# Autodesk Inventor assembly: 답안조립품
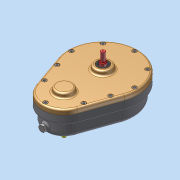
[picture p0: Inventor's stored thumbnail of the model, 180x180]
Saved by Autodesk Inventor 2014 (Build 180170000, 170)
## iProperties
Created: 2025-02
Part Number: 답안조립품
Document SubType Name: Assembly
Designer: dg
Mass: 1846.66 g
Surface Area: 1657.69 cm^2
Volume: 424.643 cm^3
Density: 4.34873 g/cm^3
Author: dg
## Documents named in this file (13)
- C:\Users\dg\Desktop\650203V1009\답안조립품.iam
- C:\Users\dg\Desktop\650203V1009\가져온 구성요소\본체\본체.ipt
- C:\Users\dg\Desktop\650203V1009\가져온 구성요소\상단 축\상단 축.ipt
- C:\Users\dg\Desktop\650203V1009\가져온 구성요소\스퍼기어A\스퍼기어A.ipt
- C:\Users\dg\Desktop\650203V1009\가져온 구성요소\오일리스 부시\오일리스 부시.ipt
- C:\Users\dg\Desktop\650203V1009\가져온 구성요소\평행키 5x5x12\평행키 5x5x12.ipt
- C:\Users\dg\Desktop\650203V1009\가져온 구성요소\스퍼기어B\스퍼기어B.ipt
- C:\Users\dg\Desktop\650203V1009\가져온 구성요소\하단 축\하단 축.ipt
- C:\Users\dg\Desktop\650203V1009\가져온 구성요소\가스켓\가스켓.ipt
- C:\Users\dg\Desktop\650203V1009\가져온 구성요소\커버\커버.ipt
- C:\Users\dg\Desktop\650203V1009\가져온 구성요소\육각 소켓 머리 볼트 M4x10\육각 소켓 머리 볼트 M4x10.ipt
- C:\Users\dg\Desktop\650203V1009\가져온 구성요소\오일 실 10 20 4\오일 실 10 20 4.ipt
- C:\Users\dg\Desktop\650203V1009\가져온 구성요소\육각 머리 볼트  M6x0.75x6\육각 머리 볼트  M6x0.75x6.ipt
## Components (2 placed, 2 different names)
1. 하단 축:1
2. 가스켓:1
